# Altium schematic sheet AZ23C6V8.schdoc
size 127 x 101 mm
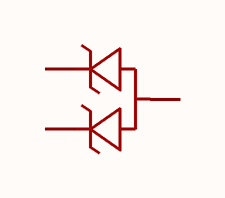
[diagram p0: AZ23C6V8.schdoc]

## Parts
U?  az23c6v8_c2991990  [SOT-23-3_L2.9-W1.3-P1.90-LS2.4-TL]  (value not drawn)

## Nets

Not connected (* = marked no-connect by the designer): U? 1(K) 2(K) 3(A)

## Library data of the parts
U? = az23c6v8_c2991990: 二极管配置:1对共阳极;稳压值(标称值):6.8V;稳压值(范围):6.4V~7.2V;耗散功率(Pd):300mW;; Manufacturer: CJ(江苏长电/长晶); AddInBom: yes; ModelId: c62791f0466c4ae2a892c056b845b0ca; ModelName: SOT-23-3P_L2.9-W1.3-H1.0-LS2.4-P0.95; ModelTransform: 98.425,114.173,0,0,0,0,-0.001,0.001,0; Diode Configuration: 1对共阳极; Zener Voltage(Nom): 6.8V; Pd - Power Dissipation: 300mW; Impedance(Zzt): 8Ω; Impedance(Zzk): 150Ω; Operating Junction Temperature Range: -65℃~+150℃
